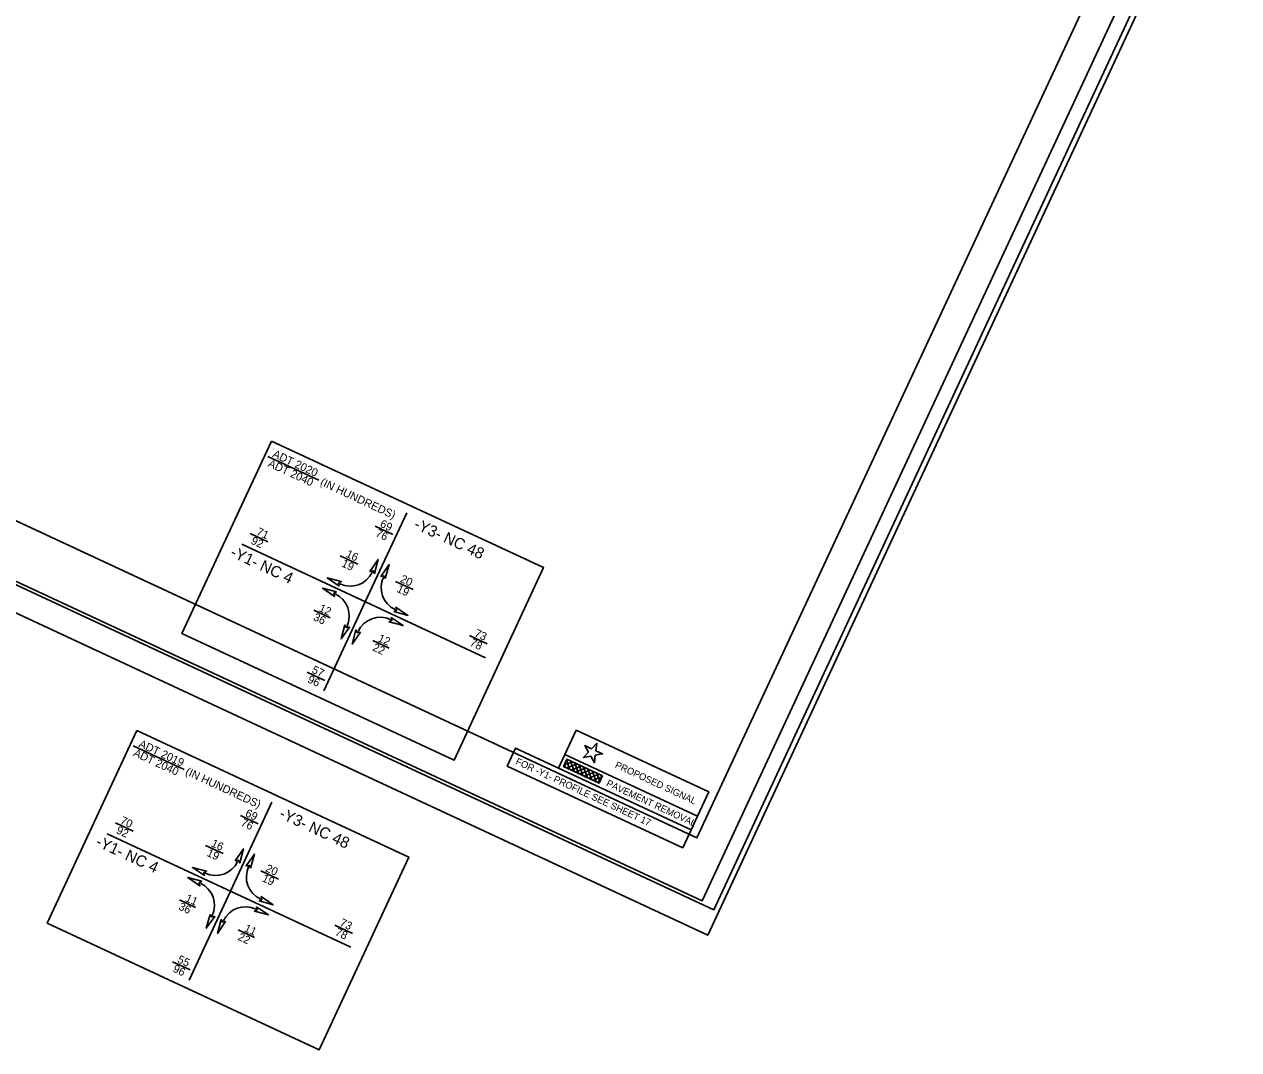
# Model space of a CAD drawing. Extents: x 2348072 to 2350078, y 842684 to 844499.
# Drawn here: x 2349016 to 2350078, y 842684 to 843581 of the extents above; entities that cross this region are included whole.
import ezdxf

# ---------------------------------------------------------------- set-up
doc = ezdxf.new("R2010")
doc.units = 0
for name, color, linetype in [('Default', 7, 'Continuous'), ('Prop DSN Text', 7, 'Continuous'), ('Prop Grid Mask', 7, 'Continuous'), ('Prop PFL Text', 7, 'Continuous'), ('Prop RDY Traffic Signal CELL', 7, 'Continuous'), ('Sheet Border Standard 30in CELL', 7, 'Continuous'), ('Sheet Clip Boundary CELL', 7, 'Continuous'), ('Sheet Plot Border Inside CELL', 7, 'Continuous'), ('Sheet Plot Border Outside CELL', 7, 'Continuous')]:
    doc.layers.add(name, color=color, linetype=linetype)

msp = doc.modelspace()

# ---------------------------------------------------------------- linework, layer by layer
at = {"layer": 'Default'}
for p, q in [((2349488, 842933.3), (2349495.3, 842935.9)), ((2349488.1, 842933.5), (2349489, 842931.1)), ((2349489.8, 842937.1), (2349491.5, 842937.7)), ((2349489.8, 842930.7), (2349499.1, 842934.1)), ((2349489.9, 842937.4), (2349492.8, 842929.3)), ((2349493.3, 842936.9), (2349496.7, 842927.5)), ((2349493.6, 842928.9), (2349503, 842932.3)), ((2349497.1, 842935.1), (2349500.5, 842925.7)), ((2349497.5, 842927.2), (2349506.8, 842930.6)), ((2349500.9, 842933.3), (2349504.3, 842923.9)), ((2349504.8, 842931.5), (2349508.2, 842922.2)), ((2349501.3, 842925.4), (2349510.7, 842928.8)), ((2349505.2, 842923.6), (2349514.5, 842927)), ((2349508.6, 842929.7), (2349512, 842920.4)), ((2349509, 842921.8), (2349518.4, 842925.2)), ((2349512.5, 842927.9), (2349515.9, 842918.6)), ((2349512.9, 842920), (2349521, 842922.9)), ((2349516.3, 842926.1), (2349519, 842918.7)), ((2349520.2, 842924.3), (2349520.8, 842922.5)), ((2349516.7, 842918.2), (2349519.2, 842919.1))]:
    msp.add_line(p, q, dxfattribs=at)
for points in [[(2349318, 843102.5), (2349325.2, 843113), (2349322, 843100.7), (2349320.6, 843103.1)], [(2349331.5, 843096.3), (2349334.9, 843108.5), (2349327.6, 843098.1), (2349330.3, 843098.6)], [(2349291.2, 843089.7), (2349280.7, 843096.8), (2349293, 843093.6), (2349290.6, 843092.2)], [(2349288.8, 843084.6), (2349276.6, 843088), (2349287, 843080.7), (2349286.5, 843083.4)], [(2349338.9, 843067.4), (2349351.2, 843064), (2349340.8, 843071.3), (2349341.3, 843068.6)], [(2349336.6, 843062.3), (2349347.1, 843055.2), (2349334.8, 843058.4), (2349337.2, 843059.8)], [(2349296.2, 843055.7), (2349292.8, 843043.5), (2349300.2, 843053.9), (2349297.4, 843053.4)], [(2349309.7, 843049.5), (2349302.6, 843039), (2349305.8, 843051.3), (2349307.2, 843048.9)], [(2349482.9, 842930.6), (2349598.8, 842876.5), (2349604.3, 842888.4), (2349488.4, 842942.5)], [(2349521.4, 842923.8), (2349490.3, 842938.3), (2349487.3, 842931.9), (2349518.4, 842917.4)], [(2349200.2, 842849.5), (2349207.4, 842860), (2349204.2, 842847.7), (2349202.8, 842850.1)], [(2349213.7, 842843.2), (2349217.1, 842855.4), (2349209.8, 842845.1), (2349212.5, 842845.5)], [(2349171, 842831.6), (2349158.8, 842835), (2349169.2, 842827.6), (2349168.7, 842830.4)], [(2349173.4, 842836.6), (2349162.9, 842843.8), (2349175.2, 842840.5), (2349172.8, 842839.1)], [(2349221.2, 842814.4), (2349233.4, 842810.9), (2349223, 842818.3), (2349223.5, 842815.5)], [(2349218.8, 842809.3), (2349229.3, 842802.2), (2349217, 842805.4), (2349219.4, 842806.8)], [(2349178.4, 842802.7), (2349175, 842790.5), (2349182.4, 842800.9), (2349179.6, 842800.4)], [(2349191.9, 842796.4), (2349184.8, 842785.9), (2349188, 842798.2), (2349189.4, 842795.8)]]:
    msp.add_lwpolyline(points, close=True, dxfattribs=at)
for centre, start, end in [((2349300.7, 843111), 245.0369, 335.0369), ((2349349.2, 843088.5), 155.0368, 245.0368), ((2349278.6, 843063.5), 335.0368, 65.0368), ((2349327.1, 843041), 65.0369, 155.0369), ((2349182.9, 842858), 245.0369, 335.0369), ((2349231.4, 842835.4), 155.0368, 245.0368), ((2349160.8, 842810.5), 335.0368, 65.0368), ((2349209.3, 842787.9), 65.0369, 155.0369)]:
    msp.add_arc(centre, 21.4, start, end, dxfattribs=at)
at = {"layer": 'Prop DSN Text'}
for p, q in [((2349228.7, 843203.1), (2349273.5, 843182.2)), ((2349350.2, 843153.8), (2349313.9, 843076)), ((2349213.4, 843135.6), (2349228.8, 843128.4)), ((2349322.6, 843142), (2349338.1, 843134.8)), ((2349206.1, 843126.2), (2349419.1, 843027)), ((2349292.1, 843116), (2349307.5, 843108.8)), ((2349340.4, 843093.8), (2349355.8, 843086.6)), ((2349269.1, 843068.5), (2349283.4, 843061.8)), ((2349313.9, 843076), (2349277.7, 842998.1)), ((2349320.7, 843042.2), (2349334.9, 843035.5)), ((2349405.1, 843046.4), (2349420.5, 843039.2)), ((2349263.2, 843014.3), (2349278.6, 843007.1)), ((2349111, 842950), (2349155.7, 842929.2)), ((2349232.4, 842900.8), (2349196.2, 842822.9)), ((2349204.8, 842889), (2349220.3, 842881.8)), ((2349095.6, 842882.6), (2349111, 842875.4)), ((2349088.3, 842873.1), (2349301.3, 842774)), ((2349174.3, 842862.9), (2349189.7, 842855.8)), ((2349222.6, 842840.7), (2349238, 842833.6)), ((2349151.4, 842815.4), (2349165.6, 842808.8)), ((2349196.2, 842822.9), (2349159.9, 842745.1)), ((2349287.3, 842793.3), (2349302.7, 842786.1)), ((2349202.9, 842789.1), (2349217.1, 842782.5)), ((2349145.4, 842761.2), (2349160.8, 842754.1))]:
    msp.add_line(p, q, dxfattribs=at)
for points in [[(2349232.1, 843216.5), (2349469.9, 843105.8), (2349391.6, 842937.4), (2349153.7, 843048.2)], [(2349114.3, 842963.5), (2349352.1, 842852.7), (2349273.8, 842684.4), (2349035.9, 842795.1)]]:
    msp.add_lwpolyline(points, close=True, dxfattribs=at)
at = {"layer": 'Prop Grid Mask'}
msp.add_lwpolyline([(2349498.3, 842963.8), (2349614.3, 842909.8), (2349604.4, 842888.5), (2349488.4, 842942.5)], close=True, dxfattribs=at)
at = {"layer": 'Prop PFL Text'}
msp.add_lwpolyline([(2349438.1, 842932.3), (2349591.5, 842860.9), (2349598.8, 842876.5), (2349445.4, 842948)], close=True, dxfattribs=at)
at = {"layer": 'Prop RDY Traffic Signal CELL'}
msp.add_lwpolyline([(2349511.9, 842947.5), (2349506, 842950.2), (2349509.1, 842944.5), (2349504.7, 842939.7), (2349511.1, 842941), (2349514.3, 842935.3), (2349515.1, 842941.8), (2349521.5, 842943), (2349515.6, 842945.8), (2349516.3, 842952.3), (2349511.9, 842947.5)], dxfattribs=at)
at = {"layer": 'Sheet Border Standard 30in CELL'}
msp.add_lwpolyline([(2350051.6, 843766.3), (2348678.7, 844405.4), (2348235.6, 843453.5), (2349608.4, 842814.4)], close=True, dxfattribs=at)
at = {"layer": 'Sheet Clip Boundary CELL'}
for points in [[(2348757.8, 844341), (2348345.6, 843455.4), (2349604, 842869.6), (2349943, 843597.8), (2349761.6, 843682.2), (2349834.9, 843839.6)], [(2349311.6, 844083.2), (2348757.8, 844341), (2348401, 843574.5), (2348593.8, 843484.7), (2348538.4, 843365.7), (2349604, 842869.6), (2349943, 843597.8), (2349761.6, 843682.2), (2349787.4, 843737.5), (2349264.1, 843981.1)]]:
    msp.add_lwpolyline(points, close=True, dxfattribs=at)
at = {"layer": 'Sheet Plot Border Inside CELL'}
msp.add_lwpolyline([(2350064.1, 843763.3), (2348538.8, 844473.3), (2348093.5, 843516.8), (2349618.8, 842806.7)], close=True, dxfattribs=at)
at = {"layer": 'Sheet Plot Border Outside CELL'}
msp.add_lwpolyline([(2350077.6, 843781.7), (2348536.5, 844499.2), (2348072.2, 843501.9), (2349613.4, 842784.5)], close=True, dxfattribs=at)

# ---------------------------------------------------------------- texts
at = {"layer": 'Prop DSN Text'}
for s, height, rotation, p in [('ADT 2020', 7, 335.0369, (2349232.3, 843202.8)), ('ADT 2040', 7, 335.0369, (2349228.4, 843194.5)), ('(IN HUNDREDS)', 7, 335.0369, (2349273.9, 843178.2)), ('69', 7, 335.0369, (2349326.2, 843141.8)), ('-Y3- NC 48', 9.8, 335.0369, (2349355.7, 843140.5)), ('92', 7, 335.0369, (2349213.4, 843127)), ('71', 7, 335.0369, (2349218.2, 843134.9)), ('76', 7, 335.0369, (2349322.3, 843133.5)), ('-Y1- NC 4', 9.8, 335.0369, (2349195.2, 843116)), ('19', 7, 335.0369, (2349292.6, 843107.1)), ('16', 7, 335.0369, (2349296.4, 843115.5)), ('19', 7, 335.0369, (2349340.9, 843084.9)), ('20', 7, 335.0369, (2349343.9, 843093.6)), ('12', 7, 335.0369, (2349272.8, 843068)), ('36', 7, 335.0369, (2349267.9, 843060.2)), ('73', 7, 335.0369, (2349408.8, 843046.1)), ('22', 7, 335.0369, (2349319.7, 843033.7)), ('12', 7, 335.0369, (2349324.4, 843041.7)), ('78', 7, 335.0369, (2349404.8, 843037.9)), ('57', 7, 335.0369, (2349266.6, 843014.2)), ('96', 7, 335.0369, (2349262.9, 843005.8)), ('ADT 2019', 7, 335.0369, (2349115.3, 842949.4)), ('ADT 2040', 7, 335.0369, (2349110.6, 842941.5)), ('(IN HUNDREDS)', 7, 335.0369, (2349156.1, 842925.2)), ('FOR -Y1- PROFILE SEE SHEET 17', 6, 335.0369, (2349444.8, 842934.3)), ('PROPOSED SIGNAL', 6, 335.0369, (2349531.8, 842931.2)), ('PAVEMENT REMOVAL', 6, 334.979, (2349524.1, 842915.3)), ('70', 7, 335.0369, (2349099.1, 842882.4)), ('69', 7, 335.0369, (2349208.4, 842888.8)), ('-Y3- NC 48', 9.8, 335.0369, (2349237.9, 842887.5)), ('92', 7, 335.0369, (2349095.6, 842873.9)), ('76', 7, 335.0369, (2349204.5, 842880.5)), ('-Y1- NC 4', 9.8, 335.0369, (2349077.4, 842863)), ('16', 7, 335.0369, (2349178.6, 842862.4)), ('19', 7, 335.0369, (2349174.8, 842854.1)), ('20', 7, 335.0369, (2349226.1, 842840.6)), ('19', 7, 335.0369, (2349223.1, 842831.9)), ('11', 7, 335.0369, (2349156, 842814.5)), ('36', 7, 335.0369, (2349150.1, 842807.2)), ('11', 7, 335.0369, (2349207.5, 842788.2)), ('73', 7, 335.0369, (2349291, 842793.1)), ('22', 7, 335.0369, (2349201.9, 842780.7)), ('78', 7, 335.0369, (2349287, 842784.8)), ('55', 7, 335.0369, (2349149.1, 842761)), ('96', 7, 335.0369, (2349145.1, 842752.8))]:
    msp.add_text(s, height=height, rotation=rotation, dxfattribs=at).set_placement(p)

doc.saveas('drawing.dxf')
